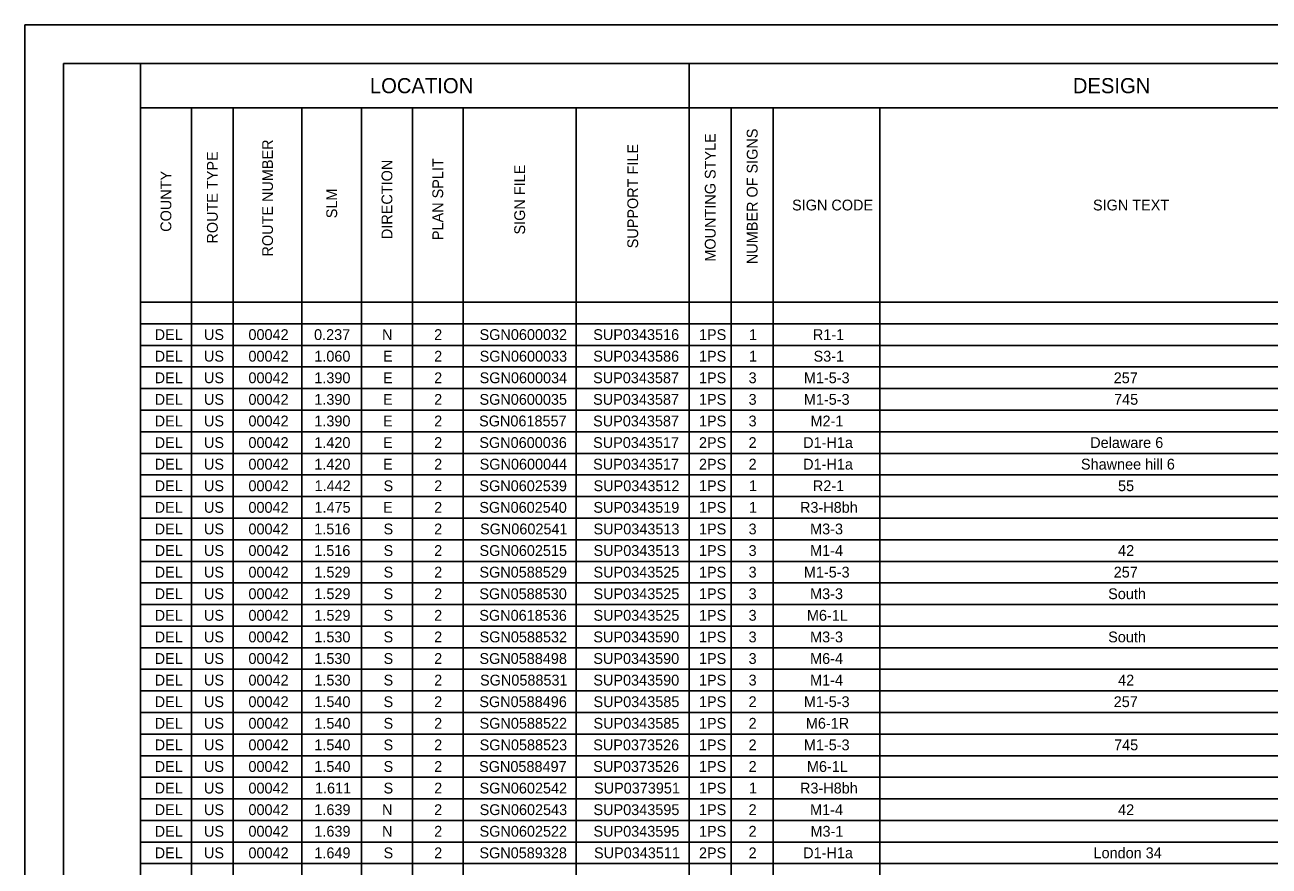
# Model space of a CAD drawing. Extents: x 0 to 34, y 0 to 22.
# Drawn here: x 0 to 16.13, y 11.09 to 22 of the extents above; entities that cross this region are included whole.
import ezdxf

# ---------------------------------------------------------------- set-up
doc = ezdxf.new("R2010")
doc.units = 0
for name, color, linetype in [('Default', 7, 'Continuous'), ('SH_Border', 7, 'Continuous'), ('SH_Cut_Line', 7, 'Continuous'), ('SH_Data', 7, 'Continuous')]:
    doc.layers.add(name, color=color, linetype=linetype)

msp = doc.modelspace()

# ---------------------------------------------------------------- linework, layer by layer
at = {"layer": 'SH_Border'}
for points in [[(0.5, 21.5), (1.5, 21.5), (1.5, 0.5), (0.5, 0.5)], [(1.5, 21.5), (33.5, 21.5), (33.5, 0.5), (1.5, 0.5)]]:
    msp.add_lwpolyline(points, close=True, dxfattribs=at)
at = {"layer": 'SH_Cut_Line'}
msp.add_lwpolyline([(0, 0), (34, 0), (34, 22), (0, 22)], close=True, dxfattribs=at)
at = {"layer": 'SH_Data'}
for p, q in [((1.5, 21.5), (32.004, 21.5)), ((8.615, 21.5), (8.615, 0.764)), ((1.5, 20.924), (28.232, 20.924)), ((1.5, 20.924), (1.5, 0.764)), ((2.159, 20.924), (2.159, 0.764)), ((2.702, 20.924), (2.702, 0.764)), ((3.592, 20.924), (3.592, 0.764)), ((4.366, 20.924), (4.366, 0.764)), ((5.025, 20.924), (5.025, 0.764)), ((5.684, 20.924), (5.684, 0.764)), ((7.149, 20.924), (7.149, 0.764)), ((9.159, 20.924), (9.159, 0.764)), ((9.702, 20.924), (9.702, 0.764)), ((11.086, 20.924), (11.086, 0.764)), ((1.5, 18.404), (32.004, 18.404)), ((1.5, 18.124), (32.004, 18.124)), ((1.5, 17.844), (32.004, 17.844)), ((1.5, 17.564), (32.004, 17.564)), ((1.5, 17.284), (32.004, 17.284)), ((1.5, 17.004), (32.004, 17.004)), ((1.5, 16.724), (32.004, 16.724)), ((1.5, 16.444), (32.004, 16.444)), ((1.5, 16.164), (32.004, 16.164)), ((1.5, 15.884), (32.004, 15.884)), ((1.5, 15.604), (32.004, 15.604)), ((1.5, 15.324), (32.004, 15.324)), ((1.5, 15.044), (32.004, 15.044)), ((1.5, 14.764), (32.004, 14.764)), ((1.5, 14.484), (32.004, 14.484)), ((1.5, 14.204), (32.004, 14.204)), ((1.5, 13.924), (32.004, 13.924)), ((1.5, 13.644), (32.004, 13.644)), ((1.5, 13.364), (32.004, 13.364)), ((1.5, 13.084), (32.004, 13.084)), ((1.5, 12.804), (32.004, 12.804)), ((1.5, 12.524), (32.004, 12.524)), ((1.5, 12.244), (32.004, 12.244)), ((1.5, 11.964), (32.004, 11.964)), ((1.5, 11.684), (32.004, 11.684)), ((1.5, 11.404), (32.004, 11.404)), ((1.5, 11.124), (32.004, 11.124))]:
    msp.add_line(p, q, dxfattribs=at)

# ---------------------------------------------------------------- texts
at = {"layer": 'Default'}
for s, height, p in [('LOCATION', 0.196, (4.474, 21.114)), ('DESIGN', 0.196, (13.589, 21.114)), ('SIGN CODE', 0.14, (9.948, 19.594)), ('SIGN TEXT', 0.14, (13.85, 19.594)), ('DEL', 0.14, (1.683, 17.914)), ('US', 0.14, (2.322, 17.914)), ('00042', 0.14, (2.899, 17.914)), ('0.237', 0.14, (3.75, 17.914)), ('N', 0.14, (4.632, 17.914)), ('2', 0.14, (5.307, 17.914)), ('SGN0600032', 0.14, (5.896, 17.914)), ('SUP0343516', 0.14, (7.37, 17.914)), ('1PS', 0.14, (8.741, 17.914)), ('1', 0.14, (9.389, 17.914)), ('R1-1', 0.14, (10.218, 17.914)), ('DEL', 0.14, (1.683, 17.634)), ('US', 0.14, (2.322, 17.634)), ('00042', 0.14, (2.899, 17.634)), ('1.060', 0.14, (3.753, 17.634)), ('E', 0.14, (4.645, 17.634)), ('2', 0.14, (5.307, 17.634)), ('SGN0600033', 0.14, (5.897, 17.634)), ('SUP0343586', 0.14, (7.37, 17.634)), ('1PS', 0.14, (8.741, 17.634)), ('1', 0.14, (9.389, 17.634)), ('S3-1', 0.14, (10.227, 17.634)), ('DEL', 0.14, (1.683, 17.354)), ('US', 0.14, (2.322, 17.354)), ('00042', 0.14, (2.899, 17.354)), ('1.390', 0.14, (3.753, 17.354)), ('E', 0.14, (4.645, 17.354)), ('2', 0.14, (5.307, 17.354)), ('SGN0600034', 0.14, (5.897, 17.354)), ('SUP0343587', 0.14, (7.368, 17.354)), ('1PS', 0.14, (8.741, 17.354)), ('3', 0.14, (9.384, 17.354)), ('M1-5-3', 0.14, (10.101, 17.354)), ('257', 0.14, (14.119, 17.354)), ('DEL', 0.14, (1.683, 17.074)), ('US', 0.14, (2.322, 17.074)), ('00042', 0.14, (2.899, 17.074)), ('1.390', 0.14, (3.753, 17.074)), ('E', 0.14, (4.645, 17.074)), ('2', 0.14, (5.307, 17.074)), ('SGN0600035', 0.14, (5.895, 17.074)), ('SUP0343587', 0.14, (7.368, 17.074)), ('1PS', 0.14, (8.741, 17.074)), ('3', 0.14, (9.384, 17.074)), ('M1-5-3', 0.14, (10.101, 17.074)), ('745', 0.14, (14.124, 17.074)), ('DEL', 0.14, (1.683, 16.794)), ('US', 0.14, (2.322, 16.794)), ('00042', 0.14, (2.899, 16.794)), ('1.390', 0.14, (3.753, 16.794)), ('E', 0.14, (4.645, 16.794)), ('2', 0.14, (5.307, 16.794)), ('SGN0618557', 0.14, (5.89, 16.794)), ('SUP0343587', 0.14, (7.368, 16.794)), ('1PS', 0.14, (8.741, 16.794)), ('3', 0.14, (9.384, 16.794)), ('M2-1', 0.14, (10.187, 16.794)), ('DEL', 0.14, (1.683, 16.514)), ('US', 0.14, (2.322, 16.514)), ('00042', 0.14, (2.899, 16.514)), ('1.420', 0.14, (3.753, 16.514)), ('E', 0.14, (4.645, 16.514)), ('2', 0.14, (5.307, 16.514)), ('SGN0600036', 0.14, (5.893, 16.514)), ('SUP0343517', 0.14, (7.368, 16.514)), ('2PS', 0.14, (8.741, 16.514)), ('2', 0.14, (9.384, 16.514)), ('D1-H1a', 0.14, (10.092, 16.514)), ('Delaware 6', 0.14, (13.814, 16.514)), ('DEL', 0.14, (1.683, 16.234)), ('US', 0.14, (2.322, 16.234)), ('00042', 0.14, (2.899, 16.234)), ('1.420', 0.14, (3.753, 16.234)), ('E', 0.14, (4.645, 16.234)), ('2', 0.14, (5.307, 16.234)), ('SGN0600044', 0.14, (5.897, 16.234)), ('SUP0343517', 0.14, (7.368, 16.234)), ('2PS', 0.14, (8.741, 16.234)), ('2', 0.14, (9.384, 16.234)), ('D1-H1a', 0.14, (10.092, 16.234)), ('Shawnee hill 6', 0.14, (13.694, 16.234)), ('DEL', 0.14, (1.683, 15.954)), ('US', 0.14, (2.322, 15.954)), ('00042', 0.14, (2.899, 15.954)), ('1.442', 0.14, (3.756, 15.954)), ('S', 0.14, (4.651, 15.954)), ('2', 0.14, (5.307, 15.954)), ('SGN0602539', 0.14, (5.894, 15.954)), ('SUP0343512', 0.14, (7.374, 15.954)), ('1PS', 0.14, (8.741, 15.954)), ('1', 0.14, (9.389, 15.954)), ('R2-1', 0.14, (10.218, 15.954)), ('55', 0.14, (14.175, 15.954)), ('DEL', 0.14, (1.683, 15.674)), ('US', 0.14, (2.322, 15.674)), ('00042', 0.14, (2.899, 15.674)), ('1.475', 0.14, (3.755, 15.674)), ('E', 0.14, (4.645, 15.674)), ('2', 0.14, (5.307, 15.674)), ('SGN0602540', 0.14, (5.893, 15.674)), ('SUP0343519', 0.14, (7.372, 15.674)), ('1PS', 0.14, (8.741, 15.674)), ('1', 0.14, (9.389, 15.674)), ('R3-H8bh', 0.14, (10.051, 15.674)), ('DEL', 0.14, (1.683, 15.394)), ('US', 0.14, (2.322, 15.394)), ('00042', 0.14, (2.899, 15.394)), ('1.516', 0.14, (3.752, 15.394)), ('S', 0.14, (4.651, 15.394)), ('2', 0.14, (5.307, 15.394)), ('SGN0602541', 0.14, (5.902, 15.394)), ('SUP0343513', 0.14, (7.374, 15.394)), ('1PS', 0.14, (8.741, 15.394)), ('3', 0.14, (9.384, 15.394)), ('M3-3', 0.14, (10.182, 15.394)), ('DEL', 0.14, (1.683, 15.114)), ('US', 0.14, (2.322, 15.114)), ('00042', 0.14, (2.899, 15.114)), ('1.516', 0.14, (3.752, 15.114)), ('S', 0.14, (4.651, 15.114)), ('2', 0.14, (5.307, 15.114)), ('SGN0602515', 0.14, (5.895, 15.114)), ('SUP0343513', 0.14, (7.374, 15.114)), ('1PS', 0.14, (8.741, 15.114)), ('3', 0.14, (9.384, 15.114)), ('M1-4', 0.14, (10.182, 15.114)), ('42', 0.14, (14.176, 15.114)), ('DEL', 0.14, (1.683, 14.834)), ('US', 0.14, (2.322, 14.834)), ('00042', 0.14, (2.899, 14.834)), ('1.529', 0.14, (3.754, 14.834)), ('S', 0.14, (4.651, 14.834)), ('2', 0.14, (5.307, 14.834)), ('SGN0588529', 0.14, (5.894, 14.834)), ('SUP0343525', 0.14, (7.373, 14.834)), ('1PS', 0.14, (8.741, 14.834)), ('3', 0.14, (9.384, 14.834)), ('M1-5-3', 0.14, (10.101, 14.834)), ('257', 0.14, (14.119, 14.834)), ('DEL', 0.14, (1.683, 14.554)), ('US', 0.14, (2.322, 14.554)), ('00042', 0.14, (2.899, 14.554)), ('1.529', 0.14, (3.754, 14.554)), ('S', 0.14, (4.651, 14.554)), ('2', 0.14, (5.307, 14.554)), ('SGN0588530', 0.14, (5.893, 14.554)), ('SUP0343525', 0.14, (7.373, 14.554)), ('1PS', 0.14, (8.741, 14.554)), ('3', 0.14, (9.384, 14.554)), ('M3-3', 0.14, (10.182, 14.554)), ('South', 0.14, (14.047, 14.554)), ('DEL', 0.14, (1.683, 14.274)), ('US', 0.14, (2.322, 14.274)), ('00042', 0.14, (2.899, 14.274)), ('1.529', 0.14, (3.754, 14.274)), ('S', 0.14, (4.651, 14.274)), ('2', 0.14, (5.307, 14.274)), ('SGN0618536', 0.14, (5.893, 14.274)), ('SUP0343525', 0.14, (7.373, 14.274)), ('1PS', 0.14, (8.741, 14.274)), ('3', 0.14, (9.384, 14.274)), ('M6-1L', 0.14, (10.141, 14.274)), ('DEL', 0.14, (1.683, 13.994)), ('US', 0.14, (2.322, 13.994)), ('00042', 0.14, (2.899, 13.994)), ('1.530', 0.14, (3.753, 13.994)), ('S', 0.14, (4.651, 13.994)), ('2', 0.14, (5.307, 13.994)), ('SGN0588532', 0.14, (5.896, 13.994)), ('SUP0343590', 0.14, (7.371, 13.994)), ('1PS', 0.14, (8.741, 13.994)), ('3', 0.14, (9.384, 13.994)), ('M3-3', 0.14, (10.182, 13.994)), ('South', 0.14, (14.047, 13.994)), ('DEL', 0.14, (1.683, 13.714)), ('US', 0.14, (2.322, 13.714)), ('00042', 0.14, (2.899, 13.714)), ('1.530', 0.14, (3.753, 13.714)), ('S', 0.14, (4.651, 13.714)), ('2', 0.14, (5.307, 13.714)), ('SGN0588498', 0.14, (5.894, 13.714)), ('SUP0343590', 0.14, (7.371, 13.714)), ('1PS', 0.14, (8.741, 13.714)), ('3', 0.14, (9.384, 13.714)), ('M6-4', 0.14, (10.182, 13.714)), ('DEL', 0.14, (1.683, 13.434)), ('US', 0.14, (2.322, 13.434)), ('00042', 0.14, (2.899, 13.434)), ('1.530', 0.14, (3.753, 13.434)), ('S', 0.14, (4.651, 13.434)), ('2', 0.14, (5.307, 13.434)), ('SGN0588531', 0.14, (5.902, 13.434)), ('SUP0343590', 0.14, (7.371, 13.434)), ('1PS', 0.14, (8.741, 13.434)), ('3', 0.14, (9.384, 13.434)), ('M1-4', 0.14, (10.182, 13.434)), ('42', 0.14, (14.176, 13.434)), ('DEL', 0.14, (1.683, 13.154)), ('US', 0.14, (2.322, 13.154)), ('00042', 0.14, (2.899, 13.154)), ('1.540', 0.14, (3.753, 13.154)), ('S', 0.14, (4.651, 13.154)), ('2', 0.14, (5.307, 13.154)), ('SGN0588496', 0.14, (5.893, 13.154)), ('SUP0343585', 0.14, (7.373, 13.154)), ('1PS', 0.14, (8.741, 13.154)), ('2', 0.14, (9.384, 13.154)), ('M1-5-3', 0.14, (10.101, 13.154)), ('257', 0.14, (14.119, 13.154)), ('DEL', 0.14, (1.683, 12.874)), ('US', 0.14, (2.322, 12.874)), ('00042', 0.14, (2.899, 12.874)), ('1.540', 0.14, (3.753, 12.874)), ('S', 0.14, (4.651, 12.874)), ('2', 0.14, (5.307, 12.874)), ('SGN0588522', 0.14, (5.896, 12.874)), ('SUP0343585', 0.14, (7.373, 12.874)), ('1PS', 0.14, (8.741, 12.874)), ('2', 0.14, (9.384, 12.874)), ('M6-1R', 0.14, (10.127, 12.874)), ('DEL', 0.14, (1.683, 12.594)), ('US', 0.14, (2.322, 12.594)), ('00042', 0.14, (2.899, 12.594)), ('1.540', 0.14, (3.753, 12.594)), ('S', 0.14, (4.651, 12.594)), ('2', 0.14, (5.307, 12.594)), ('SGN0588523', 0.14, (5.897, 12.594)), ('SUP0373526', 0.14, (7.37, 12.594)), ('1PS', 0.14, (8.741, 12.594)), ('2', 0.14, (9.384, 12.594)), ('M1-5-3', 0.14, (10.101, 12.594)), ('745', 0.14, (14.124, 12.594)), ('DEL', 0.14, (1.683, 12.314)), ('US', 0.14, (2.322, 12.314)), ('00042', 0.14, (2.899, 12.314)), ('1.540', 0.14, (3.753, 12.314)), ('S', 0.14, (4.651, 12.314)), ('2', 0.14, (5.307, 12.314)), ('SGN0588497', 0.14, (5.89, 12.314)), ('SUP0373526', 0.14, (7.37, 12.314)), ('1PS', 0.14, (8.741, 12.314)), ('2', 0.14, (9.384, 12.314)), ('M6-1L', 0.14, (10.141, 12.314)), ('DEL', 0.14, (1.683, 12.034)), ('US', 0.14, (2.322, 12.034)), ('00042', 0.14, (2.899, 12.034)), ('1.611', 0.14, (3.762, 12.034)), ('S', 0.14, (4.651, 12.034)), ('2', 0.14, (5.307, 12.034)), ('SGN0602542', 0.14, (5.896, 12.034)), ('SUP0373951', 0.14, (7.38, 12.034)), ('1PS', 0.14, (8.741, 12.034)), ('1', 0.14, (9.389, 12.034)), ('R3-H8bh', 0.14, (10.051, 12.034)), ('DEL', 0.14, (1.683, 11.754)), ('US', 0.14, (2.322, 11.754)), ('00042', 0.14, (2.899, 11.754)), ('1.639', 0.14, (3.754, 11.754)), ('N', 0.14, (4.632, 11.754)), ('2', 0.14, (5.307, 11.754)), ('SGN0602543', 0.14, (5.897, 11.754)), ('SUP0343595', 0.14, (7.373, 11.754)), ('1PS', 0.14, (8.741, 11.754)), ('2', 0.14, (9.384, 11.754)), ('M1-4', 0.14, (10.182, 11.754)), ('42', 0.14, (14.176, 11.754)), ('DEL', 0.14, (1.683, 11.474)), ('US', 0.14, (2.322, 11.474)), ('00042', 0.14, (2.899, 11.474)), ('1.639', 0.14, (3.754, 11.474)), ('N', 0.14, (4.632, 11.474)), ('2', 0.14, (5.307, 11.474)), ('SGN0602522', 0.14, (5.896, 11.474)), ('SUP0343595', 0.14, (7.373, 11.474)), ('1PS', 0.14, (8.741, 11.474)), ('2', 0.14, (9.384, 11.474)), ('M3-1', 0.14, (10.187, 11.474)), ('DEL', 0.14, (1.683, 11.194)), ('US', 0.14, (2.322, 11.194)), ('00042', 0.14, (2.899, 11.194)), ('1.649', 0.14, (3.754, 11.194)), ('S', 0.14, (4.651, 11.194)), ('2', 0.14, (5.307, 11.194)), ('SGN0589328', 0.14, (5.894, 11.194)), ('SUP0343511', 0.14, (7.38, 11.194)), ('2PS', 0.14, (8.741, 11.194)), ('2', 0.14, (9.384, 11.194)), ('D1-H1a', 0.14, (10.092, 11.194)), ('London 34', 0.14, (13.857, 11.194))]:
    msp.add_text(s, height=height, dxfattribs=at).set_placement(p)
for s, p in [('ROUTE NUMBER', (3.217, 18.996)), ('MOUNTING STYLE', (8.957, 18.93)), ('NUMBER OF SIGNS', (9.501, 18.898)), ('ROUTE TYPE', (2.501, 19.164)), ('SUPPORT FILE', (7.952, 19.103)), ('DIRECTION', (4.765, 19.222)), ('PLAN SPLIT', (5.424, 19.209)), ('SIGN FILE', (6.486, 19.282)), ('COUNTY', (1.899, 19.317)), ('SLM', (4.049, 19.493))]:
    msp.add_text(s, height=0.14, rotation=90, dxfattribs=at).set_placement(p)

doc.saveas('drawing.dxf')
